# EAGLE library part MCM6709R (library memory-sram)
MEMORY
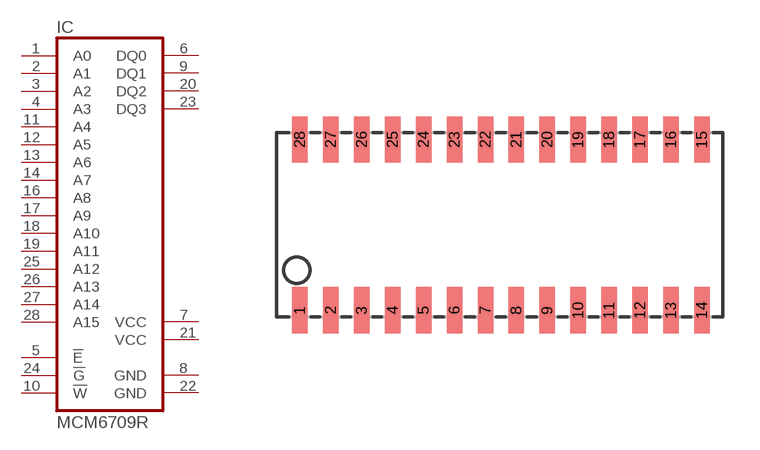
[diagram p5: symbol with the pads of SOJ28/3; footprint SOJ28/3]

Designator prefix IC

## MCM6709R  [SOJ28/3]
1  A0  in
2  A1  in
3  A2  in
4  A3  in
5  !E  in
6  DQ0
7  VCC  pwr
8  GND  pwr
9  DQ1
10  !W  in
11  A4  in
12  A5  in
13  A6  in
14  A7  in
16  A8  in
17  A9  in
18  A10  in
19  A11  in
20  DQ2
21  VCC  pwr
22  GND  pwr
23  DQ3
24  !G  in
25  A12  in
26  A13  in
27  A14  in
28  A15  in

## Footprint SOJ28/3 (pad centres in mm)
Small Outline J-Bend
smd 0.635 x 1.905: 1 -8.255,-3.505; 2 -6.985,-3.505; 3 -5.715,-3.505; 4 -4.445,-3.505; 5 -3.175,-3.505; 6 -1.905,-3.505; 7 -0.635,-3.505; 8 0.635,-3.505; 9 1.905,-3.505; 10 3.175,-3.505; 11 4.445,-3.505; 12 5.715,-3.505; 13 6.985,-3.505; 14 8.255,-3.505; 15 8.255,3.505; 16 6.985,3.505; 17 5.715,3.505; 18 4.445,3.505; 19 3.175,3.505; 20 1.905,3.505; 21 0.635,3.505; 22 -0.635,3.505; 23 -1.905,3.505; 24 -3.175,3.505; 25 -4.445,3.505; 26 -5.715,3.505; 27 -6.985,3.505; 28 -8.255,3.505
